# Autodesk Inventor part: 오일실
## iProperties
IsCustomPart: 0
Created: 2009-02
Part Number: 오일실
Material: 고무
Description: 오일-실
Document SubType Name: Modeling
Standard: KS B 2804
Designer: 한국산업디자인학원 [http://gmhk.co.kr]
Standards Organization: KS
Language: ko-KR
Size Designation: S - 17 30 8
Categories: <MemberInstance><Categories><Category DisplayName="샤프트 부품" InternalName="7f7aeb1f-a693-4053-b835-cee3144e0d98" Mnemonic="SHFT"><Category DisplayName="실링" Intern
Density: 0.93 g/cm^3
Author: pww
